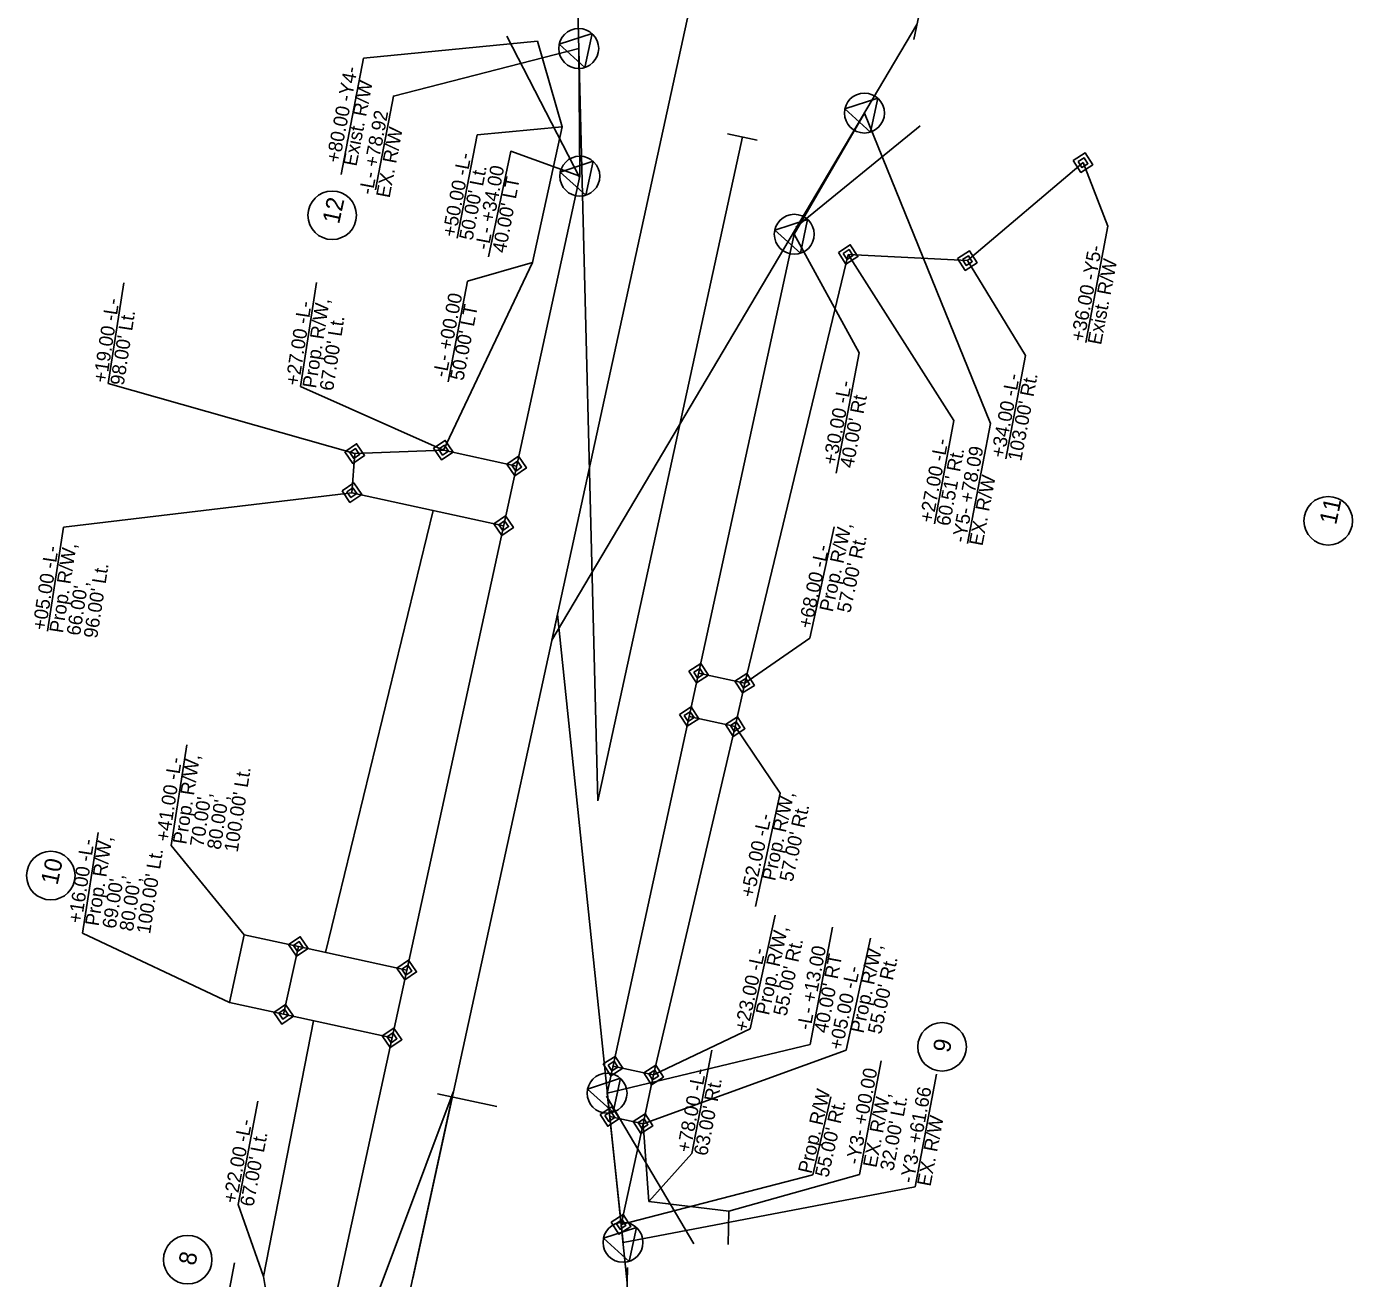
# Model space of a CAD drawing. Extents: x 1610947 to 1617684, y 899814 to 904658.
# Drawn here: x 1616169.8 to 1616647.8, y 900246.6 to 900698.1 of the extents above; entities that cross this region are included whole.
import ezdxf

# ---------------------------------------------------------------- set-up
doc = ezdxf.new("R2010")
doc.units = 0
for name, color, linetype in [('Prop Conc 1ft 6in Curb and Gutter', 7, 'Continuous'), ('Prop Conc Valley Gutter', 7, 'Continuous'), ('Prop EOT Dash', 7, 'Continuous'), ('Prop Hatching', 7, 'Continuous'), ('Prop Horizontal Alignment Curve and Spiral Data', 7, 'Continuous'), ('Prop Horizontal Alignment Direction Label', 7, 'Continuous'), ('Prop Horizontal Alignment Tick Label', 7, 'Continuous'), ('Prop Horizontal Alignment Tick Large', 7, 'Continuous'), ('Prop ROW Marker CELL', 7, 'Continuous'), ('Prop ROW RW Lines', 7, 'Continuous'), ('Prop ROW Station Offsets', 7, 'Continuous'), ('Scratch_Level_2', 7, 'Continuous'), ('Scratch_Level_3', 7, 'Continuous'), ('Scratch_Level_8', 7, 'Continuous'), ('Typical Terminator CELL', 7, 'Continuous')]:
    doc.layers.add(name, color=color, linetype=linetype)

msp = doc.modelspace()

# ---------------------------------------------------------------- linework, layer by layer
at = {"layer": 'Prop Conc 1ft 6in Curb and Gutter'}
for p, q in [((1616291.34, 900686.63), (1616354, 900692.74)), ((1616291.34, 900686.63), (1616283.25, 900644.73)), ((1616332.27, 900659.02), (1616325.08, 900621.79)), ((1616328.8, 900606.24), (1616321.8, 900569.97)), ((1616416.85, 900328.87), (1616409.67, 900291.64)), ((1616477.93, 900325.02), (1616470.16, 900284.06)), ((1616253.25, 900310.53), (1616246.06, 900273.3)), ((1616422.97, 900270.88), (1616470.16, 900284.06)), ((1616244.83, 900252.28), (1616237.75, 900215.63))]:
    msp.add_line(p, q, dxfattribs=at)
for points in [[(1616332.27, 900659.02), (1616362.91, 900661.84)], [(1616328.8, 900606.24), (1616352.27, 900612.99)], [(1616409.67, 900291.64), (1616394.14, 900274.31)], [(1616246.06, 900273.3), (1616255.19, 900247.27)]]:
    msp.add_lwpolyline(points, dxfattribs=at)
at = {"layer": 'Prop Conc Valley Gutter'}
for p, q in [((1616343.02, 900694.54), (1616369.19, 900643.7)), ((1616447.15, 900625.69), (1616491.98, 900662.29)), ((1616447.15, 900625.69), (1616491.98, 900662.29)), ((1616410.38, 900259.12), (1616378.89, 900312.37))]:
    msp.add_line(p, q, dxfattribs=at)
at = {"layer": 'Prop EOT Dash'}
for points in [[(1616547.19, 900649.73), (1616551.48, 900652.48), (1616554.22, 900648.2), (1616549.94, 900645.45)], [(1616548.95, 900649.35), (1616551.09, 900650.72), (1616552.47, 900648.58), (1616550.32, 900647.21)], [(1616462.48, 900616.61), (1616466.76, 900619.36), (1616469.51, 900615.07), (1616465.23, 900612.33)], [(1616464.24, 900616.23), (1616466.38, 900617.6), (1616467.75, 900615.46), (1616465.61, 900614.08)], [(1616505.48, 900614.41), (1616509.77, 900617.16), (1616512.51, 900612.87), (1616508.23, 900610.12)], [(1616507.24, 900614.02), (1616509.38, 900615.4), (1616510.76, 900613.25), (1616508.61, 900611.88)], [(1616316.58, 900545.95), (1616320.79, 900548.81), (1616323.65, 900544.61), (1616319.45, 900541.74)], [(1616284.59, 900544.73), (1616288.8, 900547.6), (1616291.66, 900543.39), (1616287.45, 900540.52)], [(1616286.36, 900544.4), (1616288.46, 900545.83), (1616289.89, 900543.72), (1616287.79, 900542.29)], [(1616318.35, 900545.61), (1616320.45, 900547.05), (1616321.89, 900544.94), (1616319.78, 900543.51)], [(1616342.96, 900540.2), (1616347.17, 900543.07), (1616350.03, 900538.86), (1616345.83, 900535.99)], [(1616344.73, 900539.87), (1616346.83, 900541.3), (1616348.27, 900539.19), (1616346.16, 900537.76)], [(1616283.56, 900530.63), (1616287.77, 900533.49), (1616290.64, 900529.28), (1616286.43, 900526.42)], [(1616285.33, 900530.29), (1616287.44, 900531.72), (1616288.87, 900529.62), (1616286.76, 900528.19)], [(1616338.28, 900518.71), (1616342.49, 900521.57), (1616345.35, 900517.36), (1616341.14, 900514.5)], [(1616340.05, 900518.37), (1616342.15, 900519.8), (1616343.58, 900517.7), (1616341.48, 900516.27)], [(1616408.59, 900465.62), (1616412.88, 900468.37), (1616415.62, 900464.09), (1616411.34, 900461.34)], [(1616410.35, 900465.24), (1616412.49, 900466.61), (1616413.87, 900464.47), (1616411.72, 900463.09)], [(1616425.2, 900462), (1616429.48, 900464.75), (1616432.23, 900460.47), (1616427.95, 900457.72)], [(1616426.96, 900461.62), (1616429.1, 900462.99), (1616430.48, 900460.85), (1616428.33, 900459.48)], [(1616405.19, 900449.99), (1616409.47, 900452.74), (1616412.22, 900448.45), (1616407.94, 900445.7)], [(1616406.94, 900449.6), (1616409.09, 900450.98), (1616410.46, 900448.84), (1616408.32, 900447.46)], [(1616421.79, 900446.37), (1616426.08, 900449.12), (1616428.83, 900444.83), (1616424.54, 900442.08)], [(1616423.55, 900445.98), (1616425.7, 900447.36), (1616427.07, 900445.22), (1616424.93, 900443.84)], [(1616264.29, 900366.98), (1616268.49, 900369.84), (1616271.36, 900365.64), (1616267.15, 900362.77)], [(1616266.05, 900366.64), (1616268.16, 900368.08), (1616269.59, 900365.97), (1616267.49, 900364.54)], [(1616303.37, 900358.46), (1616307.58, 900361.33), (1616310.44, 900357.12), (1616306.23, 900354.26)], [(1616305.14, 900358.13), (1616307.24, 900359.56), (1616308.67, 900357.46), (1616306.57, 900356.02)], [(1616258.96, 900342.55), (1616263.17, 900345.42), (1616266.04, 900341.21), (1616261.83, 900338.34)], [(1616260.73, 900342.22), (1616262.84, 900343.65), (1616264.27, 900341.54), (1616262.17, 900340.11)], [(1616298.05, 900334.04), (1616302.26, 900336.9), (1616305.12, 900332.69), (1616300.91, 900329.83)], [(1616299.82, 900333.7), (1616301.92, 900335.13), (1616303.35, 900333.03), (1616301.25, 900331.6)], [(1616377.73, 900323.94), (1616382.01, 900326.69), (1616384.76, 900322.41), (1616380.48, 900319.66)], [(1616379.48, 900323.56), (1616381.63, 900324.93), (1616383, 900322.79), (1616380.86, 900321.42)], [(1616392.38, 900320.75), (1616396.67, 900323.5), (1616399.41, 900319.22), (1616395.13, 900316.47)], [(1616394.14, 900320.37), (1616396.28, 900321.74), (1616397.66, 900319.6), (1616395.51, 900318.22)], [(1616376.59, 900305.77), (1616380.87, 900308.52), (1616383.62, 900304.23), (1616379.34, 900301.48)], [(1616378.34, 900305.39), (1616380.49, 900306.76), (1616381.86, 900304.62), (1616379.72, 900303.24)], [(1616388.55, 900303.16), (1616392.83, 900305.91), (1616395.58, 900301.63), (1616391.3, 900298.88)], [(1616390.31, 900302.78), (1616392.45, 900304.15), (1616393.82, 900302.01), (1616391.68, 900300.64)], [(1616380.64, 900266.86), (1616384.92, 900269.61), (1616387.67, 900265.32), (1616383.39, 900262.57)], [(1616382.4, 900266.47), (1616384.54, 900267.85), (1616385.91, 900265.71), (1616383.77, 900264.33)]]:
    msp.add_lwpolyline(points, close=True, dxfattribs=at)
at = {"layer": 'Prop Hatching'}
for centre in [(1616280.02, 900629.98), (1616639.09, 900519.82), (1616178.56, 900391.88), (1616499.88, 900330.11), (1616227.92, 900253.37)]:
    msp.add_circle(centre, 8.75, dxfattribs=at)
at = {"layer": 'Prop Horizontal Alignment Curve and Spiral Data'}
for p, q in [((1616460.93, 900517.67), (1616452.17, 900477.55)), ((1616441.48, 900421.54), (1616425.31, 900445.6)), ((1616441.48, 900421.54), (1616432.58, 900380.78)), ((1616439.69, 900377.66), (1616430.74, 900336.65)), ((1616474.13, 900369.32), (1616465.3, 900328.87)), ((1616465.3, 900328.87), (1616392.07, 900302.4))]:
    msp.add_line(p, q, dxfattribs=at)
for points in [[(1616452.17, 900477.55), (1616428.72, 900461.23)], [(1616430.74, 900336.65), (1616395.9, 900319.98)]]:
    msp.add_lwpolyline(points, dxfattribs=at)
at = {"layer": 'Prop Horizontal Alignment Direction Label'}
for p, q in [((1616509, 900613.64), (1616550.71, 900648.97)), ((1616428.72, 900461.23), (1616466, 900615.84)), ((1616466, 900615.84), (1616509, 900613.64)), ((1616395.9, 900319.98), (1616425.31, 900445.6)), ((1616384.16, 900266.09), (1616392.07, 900302.4))]:
    msp.add_line(p, q, dxfattribs=at)
at = {"layer": 'Prop Horizontal Alignment Tick Label'}
for p, q in [((1616559.63, 900626), (1616551.66, 900584.08)), ((1616529.95, 900579.41), (1616522.87, 900542.15)), ((1616504.16, 900556), (1616497.09, 900518.75)), ((1616459.8, 900312.08), (1616453.34, 900284))]:
    msp.add_line(p, q, dxfattribs=at)
for points in [[(1616559.63, 900626), (1616550.71, 900648.97)], [(1616504.16, 900556), (1616466, 900615.84)], [(1616529.95, 900579.41), (1616509, 900613.64)], [(1616453.34, 900284), (1616384.16, 900266.09)]]:
    msp.add_lwpolyline(points, dxfattribs=at)
at = {"layer": 'Prop Horizontal Alignment Tick Large'}
for p, q in [((1616428.72, 900461.23), (1616412.11, 900464.85)), ((1616425.31, 900445.6), (1616428.72, 900461.23)), ((1616408.7, 900449.22), (1616425.31, 900445.6)), ((1616381.24, 900323.18), (1616395.9, 900319.98)), ((1616392.07, 900302.4), (1616395.9, 900319.98)), ((1616380.1, 900305), (1616392.07, 900302.4))]:
    msp.add_line(p, q, dxfattribs=at)
at = {"layer": 'Prop ROW Marker CELL'}
for p, q in [((1616368.88, 900690.13), (1616368.88, 900690.13)), ((1616471.89, 900666.84), (1616471.89, 900666.84)), ((1616550.71, 900648.97), (1616550.71, 900648.97)), ((1616369.28, 900644.08), (1616369.28, 900644.08)), ((1616446.59, 900623.14), (1616446.59, 900623.14)), ((1616466, 900615.84), (1616466, 900615.84)), ((1616509, 900613.64), (1616509, 900613.64)), ((1616288.13, 900544.06), (1616288.13, 900544.06)), ((1616320.12, 900545.28), (1616320.12, 900545.28)), ((1616346.5, 900539.53), (1616346.5, 900539.53)), ((1616287.1, 900529.95), (1616287.1, 900529.95)), ((1616341.82, 900518.03), (1616341.82, 900518.03)), ((1616412.11, 900464.85), (1616412.11, 900464.85)), ((1616428.72, 900461.23), (1616428.72, 900461.23)), ((1616408.7, 900449.22), (1616408.7, 900449.22)), ((1616425.31, 900445.6), (1616425.31, 900445.6)), ((1616267.82, 900366.31), (1616267.82, 900366.31)), ((1616306.91, 900357.79), (1616306.91, 900357.79)), ((1616262.5, 900341.88), (1616262.5, 900341.88)), ((1616301.58, 900333.37), (1616301.58, 900333.37)), ((1616381.24, 900323.18), (1616381.24, 900323.18)), ((1616395.9, 900319.98), (1616395.9, 900319.98)), ((1616379.11, 900313.41), (1616379.11, 900313.41)), ((1616380.1, 900305), (1616380.1, 900305)), ((1616392.07, 900302.4), (1616392.07, 900302.4)), ((1616384.16, 900266.09), (1616384.16, 900266.09)), ((1616384.85, 900259.62), (1616384.85, 900259.62))]:
    msp.add_line(p, q, dxfattribs=at)
for points in [[(1616371.1, 900683.27), (1616361.83, 900691.63), (1616373.7, 900695.5)], [(1616474.11, 900659.98), (1616464.85, 900668.34), (1616476.71, 900672.21)], [(1616371.5, 900637.22), (1616362.23, 900645.57), (1616374.1, 900649.44)], [(1616448.81, 900616.28), (1616439.55, 900624.64), (1616451.41, 900628.51)], [(1616381.34, 900306.54), (1616372.07, 900314.9), (1616383.93, 900318.77)], [(1616387.07, 900252.75), (1616377.8, 900261.11), (1616389.67, 900264.98)]]:
    msp.add_lwpolyline(points, close=True, dxfattribs=at)
for centre in [(1616368.88, 900690.13), (1616471.89, 900666.84), (1616369.28, 900644.08), (1616446.59, 900623.14), (1616379.11, 900313.41), (1616384.85, 900259.62)]:
    msp.add_circle(centre, 7.2, dxfattribs=at)
at = {"layer": 'Prop ROW RW Lines'}
for p, q in [((1616368.88, 900690.13), (1616369.28, 900644.08)), ((1616446.59, 900623.14), (1616471.89, 900666.84)), ((1616260.71, 900145.77), (1616369.28, 900644.08)), ((1616379.11, 900313.41), (1616446.59, 900623.14)), ((1616384.85, 900259.62), (1616379.11, 900313.41)), ((1616384.85, 900259.62), (1616379.19, 900313.75))]:
    msp.add_line(p, q, dxfattribs=at)
at = {"layer": 'Prop ROW Station Offsets'}
for p, q in [((1616471.89, 900666.84), (1616517.32, 900554.91)), ((1616446.59, 900623.14), (1616469.98, 900580.38)), ((1616469.98, 900580.38), (1616461.75, 900537.04)), ((1616517.32, 900554.91), (1616509.09, 900511.57)), ((1616460.35, 900373.32), (1616452.3, 900330.92)), ((1616379.11, 900313.41), (1616452.3, 900330.92)), ((1616497.9, 900320.21), (1616490.19, 900279.59)), ((1616384.85, 900259.62), (1616490.19, 900279.59))]:
    msp.add_line(p, q, dxfattribs=at)
for points in [[(1616368.88, 900690.13), (1616302.07, 900672.96), (1616295.66, 900639.2)], [(1616369.28, 900644.08), (1616344.41, 900653.06), (1616336.4, 900615.06)]]:
    msp.add_lwpolyline(points, dxfattribs=at)
at = {"layer": 'Scratch_Level_2'}
for p, q in [((1616375.73, 900418.83), (1616368.26, 900714.52)), ((1616491.95, 900704.16), (1616489.69, 900693.39)), ((1616427.88, 900658.22), (1616375.73, 900418.83)), ((1616422.5, 900659.39), (1616433.25, 900657.05)), ((1616309.03, 900246.59), (1616361.19, 900485.97)), ((1616386.37, 900245.08), (1616361.19, 900485.97)), ((1616236.81, 900081.92), (1616323.66, 900313.74)), ((1616271.51, 900074.36), (1616323.66, 900313.74)), ((1616339.42, 900308.55), (1616317.92, 900313.23)), ((1616386.47, 900250.58), (1616386.26, 900239.59))]:
    msp.add_line(p, q, dxfattribs=at)
msp.add_lwpolyline([(1616411.32, 900716.1), (1616359.17, 900476.71), (1616490.82, 900698.78)], dxfattribs=at)
at = {"layer": 'Scratch_Level_3'}
for p, q in [((1616362.91, 900661.84), (1616354, 900692.74)), ((1616352.27, 900612.99), (1616362.91, 900661.84)), ((1616320.12, 900545.28), (1616352.27, 900612.99)), ((1616277.59, 900364.18), (1616316.41, 900523.57)), ((1616242.96, 900346.14), (1616248.28, 900370.56)), ((1616248.28, 900370.56), (1616267.82, 900366.31)), ((1616242.96, 900346.14), (1616262.5, 900341.88)), ((1616255.19, 900247.27), (1616273.25, 900339.54)), ((1616394.14, 900274.31), (1616392.07, 900302.4)), ((1616422.97, 900270.88), (1616394.14, 900274.31)), ((1616422.73, 900258.88), (1616422.97, 900270.88)), ((1616262.86, 900202.61), (1616255.19, 900247.27))]:
    msp.add_line(p, q, dxfattribs=at)
at = {"layer": 'Scratch_Level_8'}
for p, q in [((1616204.89, 900605.57), (1616199.29, 900569.27)), ((1616274.38, 900605.72), (1616268.59, 900568.25)), ((1616183.15, 900517.47), (1616177.37, 900479.99)), ((1616227.61, 900439), (1616222.01, 900402.71)), ((1616195.65, 900407.42), (1616190.05, 900371.13)), ((1616222.01, 900402.71), (1616248.28, 900370.56)), ((1616190.05, 900371.13), (1616242.96, 900346.14))]:
    msp.add_line(p, q, dxfattribs=at)
for points in [[(1616199.29, 900569.27), (1616288.13, 900544.06)], [(1616268.59, 900568.25), (1616320.12, 900545.28)], [(1616183.15, 900517.47), (1616287.1, 900529.95)]]:
    msp.add_lwpolyline(points, dxfattribs=at)
at = {"layer": 'Typical Terminator CELL'}
for p, q in [((1616287.1, 900529.95), (1616288.13, 900544.06)), ((1616288.13, 900544.06), (1616320.12, 900545.28)), ((1616346.5, 900539.53), (1616320.12, 900545.28)), ((1616341.82, 900518.03), (1616287.1, 900529.95)), ((1616262.5, 900341.88), (1616267.82, 900366.31)), ((1616306.91, 900357.79), (1616267.82, 900366.31)), ((1616301.58, 900333.37), (1616262.5, 900341.88))]:
    msp.add_line(p, q, dxfattribs=at)

# ---------------------------------------------------------------- texts
at = {"layer": 'Prop Conc 1ft 6in Curb and Gutter'}
for s, rotation, p in [('+80.00 -Y4-', 79.0727, (1616282.61, 900648.63)), ('Exist. R/W', 79.0727, (1616288.75, 900647.44)), ('+50.00 -L-', 79.0727, (1616324.47, 900621.91)), ("50.00' Lt.", 79.0727, (1616330.6, 900620.72)), ('-L- +00.00', 79.0727, (1616321.16, 900571.31)), ("50.00' LT", 79.0727, (1616327.3, 900570.13)), ('+78.00 -L-', 79.0727, (1616409.05, 900291.76)), ('-Y3- +00.00', 79.2494, (1616470.06, 900287.47)), ("63.00' Rt.", 79.0727, (1616415.19, 900290.58)), ('EX. R/W,', 79.2494, (1616476.2, 900286.31)), ("32.00' Lt.", 79.2494, (1616482.34, 900285.14)), ('+22.00 -L-', 79.0727, (1616245.44, 900273.42)), ("67.00' Lt.", 79.0727, (1616251.58, 900272.24))]:
    msp.add_text(s, height=5, rotation=rotation, dxfattribs=at).set_placement(p)
at = {"layer": 'Prop Hatching'}
for s, p in [('12', (1616282.48, 900626.57)), ('11', (1616641.92, 900518.14)), ('10', (1616180.97, 900388.24)), ('9', (1616502.56, 900327.71)), ('8', (1616230.59, 900250.97))]:
    msp.add_text(s, height=6.25, rotation=77.7167, dxfattribs=at).set_placement(p)
at = {"layer": 'Prop Horizontal Alignment Curve and Spiral Data'}
for s, p in [('Prop. R/W,', (1616460.43, 900486.68)), ('+68.00 -L-', (1616452.72, 900480.65)), ("57.00' Rt.", (1616466.75, 900486.33)), ('Prop. R/W,', (1616439.69, 900389.72)), ('+52.00 -L-', (1616431.98, 900383.69)), ("57.00' Rt.", (1616446.01, 900389.37)), ('Prop. R/W,', (1616437.46, 900341.28)), ("55.00' Rt.", (1616443.78, 900340.93)), ('Prop. R/W,', (1616471.54, 900334.76)), ('+23.00 -L-', (1616429.75, 900335.25)), ("55.00' Rt.", (1616477.86, 900334.41)), ('+05.00 -L-', (1616463.83, 900328.73))]:
    msp.add_text(s, height=5, rotation=77.6862, dxfattribs=at).set_placement(p)
at = {"layer": 'Prop Horizontal Alignment Tick Label'}
for s, rotation, p in [('+36.00 -Y5-', 79.2494, (1616551.05, 900584.19)), ('Exist. R/W', 79.2494, (1616557.19, 900583.03)), ('+34.00 -L-', 79.2494, (1616522.26, 900542.27)), ("103.00' Rt.", 79.2494, (1616528.4, 900541.1)), ('+27.00 -L-', 79.2494, (1616496.48, 900518.86)), ("60.51' Rt.", 79.2494, (1616502.62, 900517.7)), ('Prop. R/W', 77.0556, (1616452.73, 900284.14)), ("55.00' Rt.", 77.0556, (1616458.82, 900282.74))]:
    msp.add_text(s, height=5, rotation=rotation, dxfattribs=at).set_placement(p)
at = {"layer": 'Prop ROW Station Offsets'}
for s, p in [('-L- +78.92', (1616294.54, 900637.19)), ('EX. R/W', (1616300.68, 900636.02)), ('-L- +34.00', (1616336.37, 900617.3)), ("40.00' LT", (1616342.51, 900616.13)), ('+30.00 -L-', (1616461.7, 900539.75)), ("40.00' Rt", (1616467.84, 900538.58)), ('-Y5- +78.09', (1616508.29, 900511.7)), ('EX. R/W', (1616514.43, 900510.53)), ('-L- +13.00', (1616452.39, 900335.95)), ("40.00' RT", (1616458.53, 900334.79)), ('-Y3- +61.66', (1616489.56, 900280.73)), ('EX. R/W', (1616495.7, 900279.57))]:
    msp.add_text(s, height=5, rotation=79.2494, dxfattribs=at).set_placement(p)
at = {"layer": 'Scratch_Level_8'}
for s, p in [('+19.00 -L-', (1616198.67, 900569.37)), ('+27.00 -L-', (1616267.98, 900568.35)), ('Prop. R/W,', (1616274.15, 900567.39)), ("98.00' Lt.", (1616204.85, 900568.42)), ("67.00' Lt.", (1616280.33, 900566.44)), ('+05.00 -L-', (1616176.75, 900480.09)), ('Prop. R/W,', (1616182.92, 900479.13)), ("96.00' Lt.", (1616195.28, 900477.23)), ("66.00',", (1616189.1, 900478.18)), ('+41.00 -L-', (1616221.23, 900403.88)), ('Prop. R/W,', (1616227.41, 900402.93)), ("100.00' Lt.", (1616245.94, 900400.07)), ("70.00',", (1616233.59, 900401.98)), ("80.00',", (1616239.76, 900401.02)), ('+16.00 -L-', (1616189.64, 900374.42)), ('Prop. R/W,', (1616195.82, 900373.46)), ("100.00' Lt.", (1616214.35, 900370.6)), ("69.00',", (1616201.99, 900372.51)), ("80.00',", (1616208.17, 900371.56))]:
    msp.add_text(s, height=5, rotation=81.2258, dxfattribs=at).set_placement(p)

doc.saveas('drawing.dxf')
